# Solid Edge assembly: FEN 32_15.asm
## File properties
Title: Zylinder
Author: bmolnar
Template: iso assembly.asm
Last saved by: bmolnar
Revision: 12
Application: Solid Edge
Username: bmolnar
Dokumentum tartalom típus: 1
Document Number: FEN 32/15
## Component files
Kolbenstange.par
Profilrohr.par
Kit_1.par
Kit_2.par
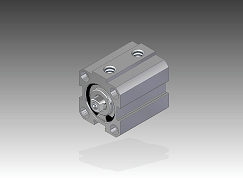
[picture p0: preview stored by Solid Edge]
